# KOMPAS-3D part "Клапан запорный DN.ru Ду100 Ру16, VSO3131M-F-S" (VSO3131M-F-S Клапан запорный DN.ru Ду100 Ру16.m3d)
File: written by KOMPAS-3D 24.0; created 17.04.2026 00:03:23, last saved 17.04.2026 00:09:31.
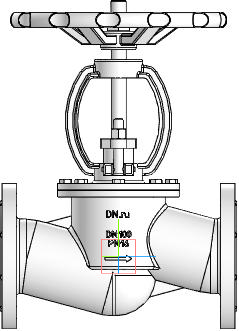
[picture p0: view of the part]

Document properties: Автор: R2D2; Полное имя файла: E:\Работа\Зайцев\VSO3131M-F-S Клапан запорный DN.ru Ду15-100 Ру16\DN100\VSO3131M-F-S Клапан запорный DN.ru Ду100 Ру16.m3d

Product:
- Part/product: Клапан запорный DN.ru Ду100 Ру16  | designation VSO3131M-F-S
    Масса: 26
    Раздел спецификации: Прочие изделия
    Примечание: D090-02954

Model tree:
1. Операция без истории:2

Referenced files in C:\Program Files\ASCON\KOMPAS-3D v24\Libs\Pipeline\: StylesTemplate.a3d, TemplateHPH, InsulationStylesTemplate.a3d, Insulation
Referenced files in C:\Program Files\ASCON\KOMPAS-3D v24\Templates\: Констр. чертеж А3 гориз. перв. лист.cdt
Referenced files in E:\Работа\Зайцев\VSO3131M-F-S Клапан запорный DN.ru Ду15-100 Ру16\DN100\исходные материалы\: 
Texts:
  Отводы ГОСТ 17375-2001
  Констр. чертеж А3 гориз. перв. лист.cdt
  VSO3131M-F-S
